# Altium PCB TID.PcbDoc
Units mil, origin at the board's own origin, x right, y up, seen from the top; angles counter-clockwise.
Board outline 2300 x 2000 mil, 2 copper layers (Top Layer, Bottom Layer), stack 62 mil thick; 70 components, 52 nets, 249 pads, 57 vias.
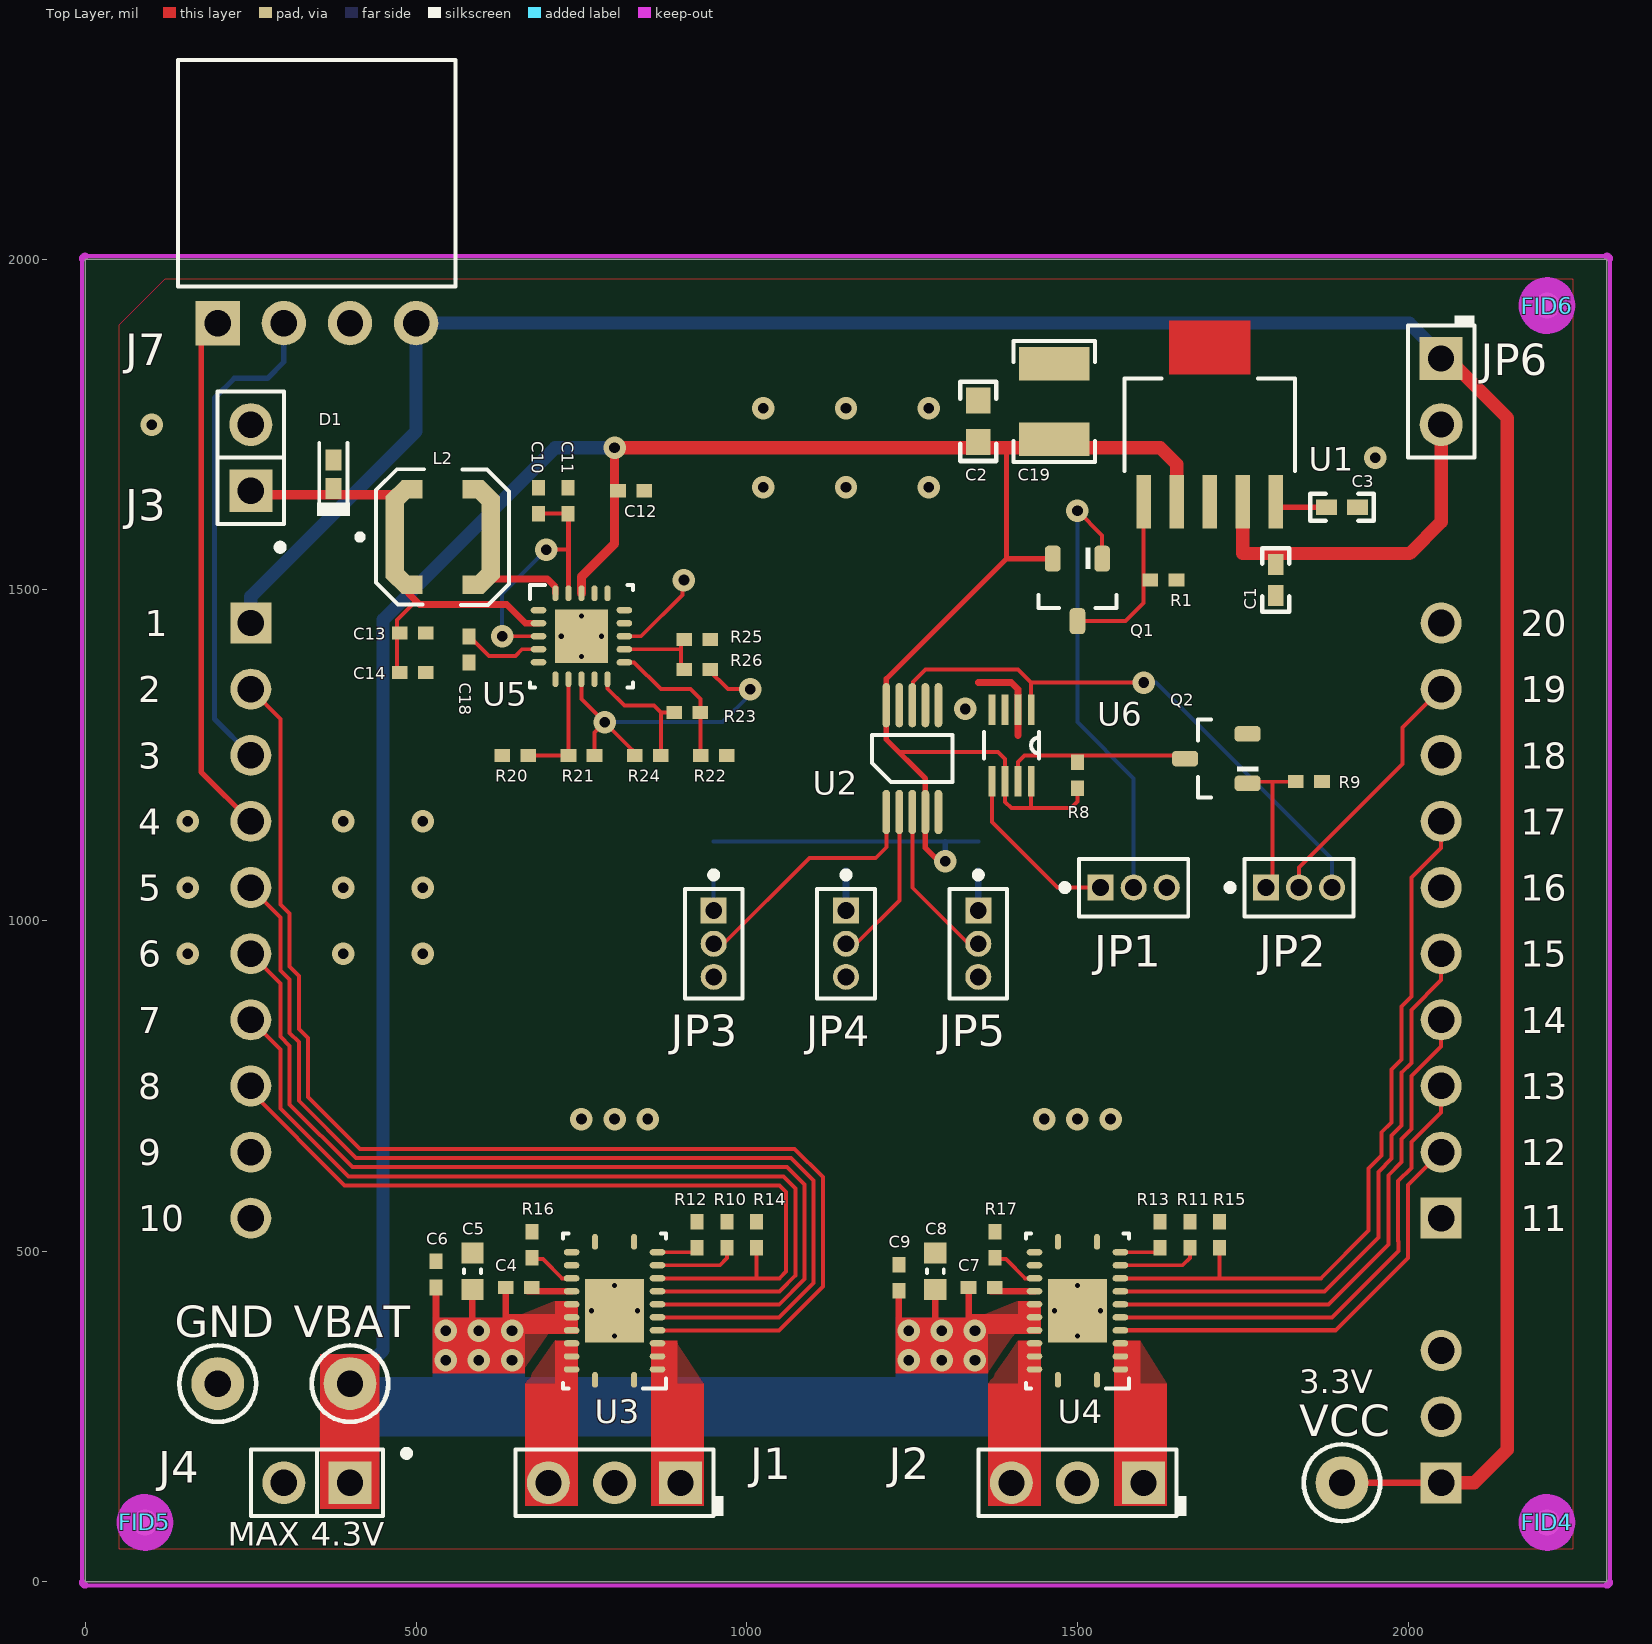
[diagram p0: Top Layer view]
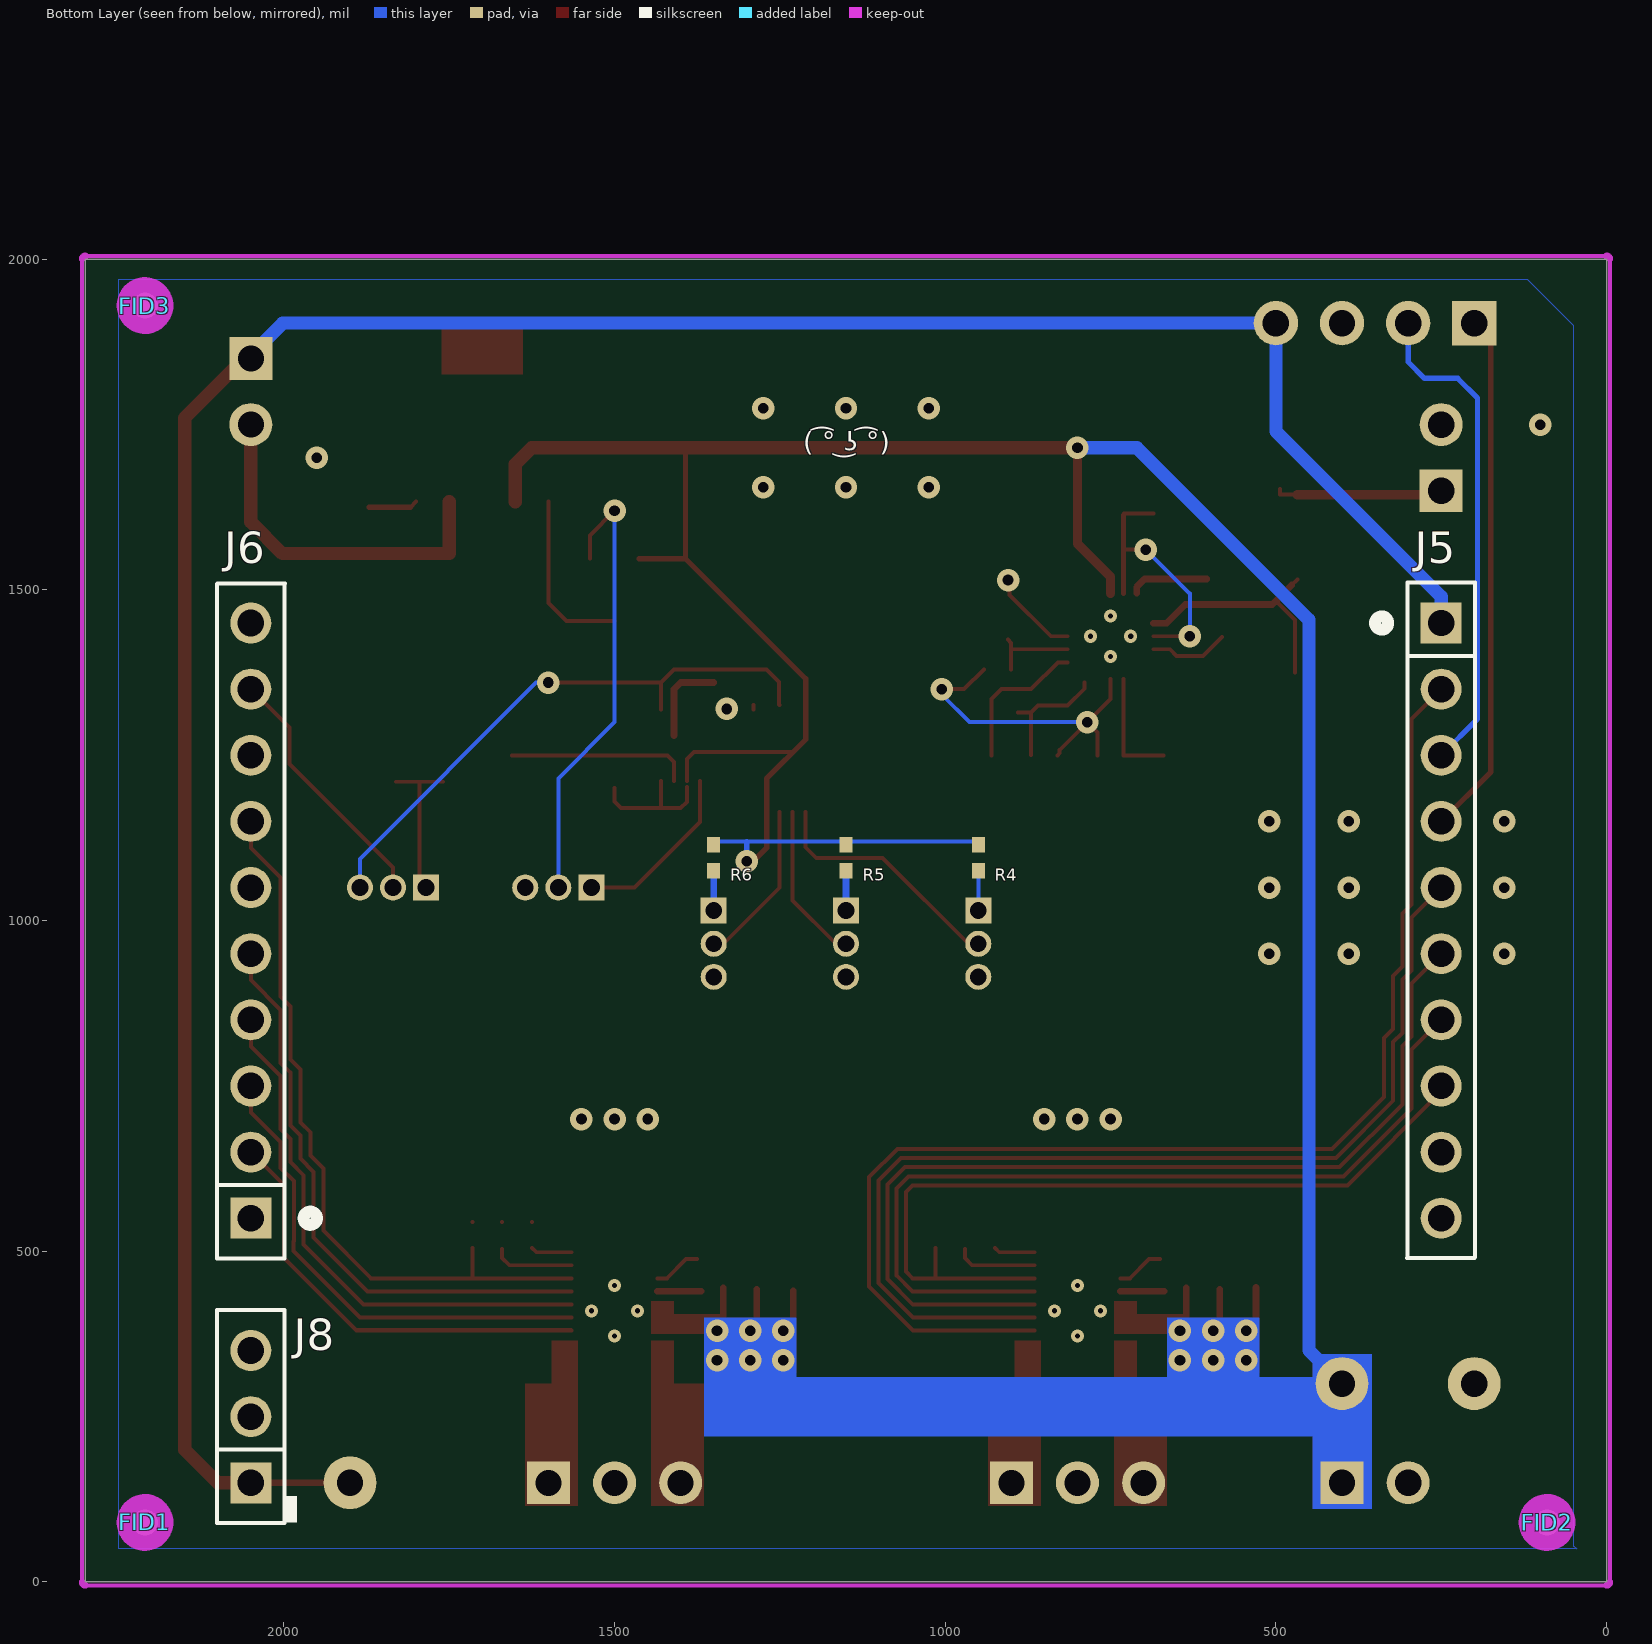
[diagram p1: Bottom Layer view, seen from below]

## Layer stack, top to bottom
Top Solder: solder mask 0.4, Solder Resist, Dk 3.5
Top Layer: signal copper 1.4
Dielectric1: core 59.2, FR-4, Dk 4.8
Bottom Layer: signal copper 1.4
Bottom Solder: solder mask 0.4, Solder Resist, Dk 3.5

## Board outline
0,0 2300,0 2300,2000 0,2000

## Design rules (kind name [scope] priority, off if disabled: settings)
AcuteAngle [All] p1: minimum=4.50000000000000E+0001 checktracksonly=FALSE
AssemblyTestPointUsage [All] p1: valid=2
Clearance Clearance_Keepouts [((IsTrack Or IsArc) And Not InPoly) And IsFree and IsKeepOut vs ((IsTrack Or IsArc) And Not InPoly) And IsFree and IsKeepOut] p1: gap=0
Clearance Clearance_BoardEdge_MountingHoles [OnCopper and InComponentClass('Mounting Holes') vs IsKeepOut] p2: gap=40
Clearance Clearance_BoardEdge_Poly [OnCopper and InPoly vs IsKeepOut] p3: gap=25
Clearance Clearance_BoardEdge [OnCopper and Not InComponentClass('Logo') and not InComponentClass('FiducialMark') and not InRegion(1000,500,4000,800) and Not IsKeepout vs IsKeepOut] p4: gap=30
Clearance Clearance_Poly [InPolygon] p5: gap=10
Clearance [All] p6: gap=7.87
ComponentClearance ComponentClearance_MountingHoles_FiducialMarks [InComponentClass('Mounting Holes') vs InComponentClass('FiducialMark')] p1: gap=50 collisioncheckmode=3 verticalgap=10 showdistances=FALSE
ComponentClearance ComponentClearance_Shunt [InComponentClass('Header') vs InComponentClass('Shunt')] p2: gap=0 collisioncheckmode=3 verticalgap=0 showdistances=FALSE
ComponentClearance ComponentClearance_Logo [InComponentClass('Logo')] p3: gap=50 collisioncheckmode=3 verticalgap=10 showdistances=FALSE
ComponentClearance ComponentClearance_ScrewToNut [(HasFootprint('NY PMS 440 0025 PH')) vs (HasFootprint('Keystone_1902C'))] p4: gap=5 collisioncheckmode=3 verticalgap=10 showdistances=FALSE
ComponentClearance ComponentClearance_MountingHoles [InComponentClass('Mounting Holes')] p5: gap=250 collisioncheckmode=3 verticalgap=100000 showdistances=FALSE
ComponentClearance ComponentClearance_SmallPassives [HasFootprint('0201*') or HasFootprint('0402*') or HasFootprint('0508') or HasFootprint('0603*') or HasFootprint('0612') or HasFootprint('0805*') or HasFootprint('0815*') or HasFootprint('0830*') or HasFootprint('1206*') or HasFootprint('1210*') or HasFootprint('1808*') or HasFootprint('1812*') or HasFootprint('1825*') or HasFootprint('2010*') or HasFootprint('2220*') or HasFootprint('2225*') or HasFootprint('2512*') or HasFootprint('2728*') or HasFootprint('3518*') vs HasFootprint('0201*') or HasFootprint('0402*') or HasFootprint('0508') or HasFootprint('0603*') or HasFootprint('0612') or HasFootprint('0805*') or HasFootprint('0815*') or HasFootprint('0830*') or HasFootprint('1206*') or HasFootprint('1210*') or HasFootprint('1808*') or HasFootprint('1812*') or HasFootprint('1825*') or HasFootprint('2010*') or HasFootprint('2220*') or HasFootprint('2225*') or HasFootprint('2512*') or HasFootprint('2728*') or HasFootprint('3518*')] p6: gap=20 collisioncheckmode=3 verticalgap=10 showdistances=FALSE
ComponentClearance ComponentClearance_THtoSMT [IsThruComponent vs IsSMTComponent] p7: gap=50 collisioncheckmode=3 verticalgap=30 showdistances=FALSE
ComponentClearance ComponentClearance_THtoTH [IsThruComponent vs IsThruComponent] p8: gap=50 collisioncheckmode=3 verticalgap=30 showdistances=FALSE
ComponentClearance [All] p9: gap=40 collisioncheckmode=3 verticalgap=10 showdistances=FALSE
DiffPairsRouting [All] p1: maxlimit=100 minlimit=10 mostfreqgap=10 toplayer_minwidth=15 toplayer_maxwidth=15 toplayer_prefwidth=15 bottomlayer_minwidth=15 bottomlayer_maxwidth=15 bottomlayer_prefwidth=15 maxuncoupledlength=1000
FabricationTestPointUsage TestPointUsage [All] p1: valid=2 allowmultiple=FALSE
FabricationTestpoint Testpoint [All] p1: side=3 testpointundercomponent=TRUE minsize=40 maxsize=100 preferedsize=60 minholesize=0 maxholesize=40 preferedholesize=32 testpointgrid=1 allowsidetop=TRUE allowsidebottom=TRUE usegrid=TRUE gridtolerance=0.01
FanoutControl Fanout_LCC [IsLCC] p1: bgadir=Out bgaviamode=Centered fanoutstyle=Auto fanoutdirection=Alternating viagrid=1 // Fanout_LCC (Default Rule)
FanoutControl Fanout_BGA [IsBGA] p2: bgadir=Out bgaviamode=Centered fanoutstyle=Auto fanoutdirection=Alternating viagrid=1 // Fanout_BGA (Default Rule)
FanoutControl Fanout_Default [All] p4: bgadir=Out bgaviamode=Centered fanoutstyle=Auto fanoutdirection=Alternating viagrid=1 // Fanout_Default (Default Rule)
FanoutControl Fanout_Small [(CompPinCount < 5)] p5: bgadir=Out bgaviamode=Centered fanoutstyle=Auto fanoutdirection=OutThenIn viagrid=1 // Fanout_Small (Default Rule)
HoleSize [All] p1: absolutevalues=TRUE maxlimit=251 minlimit=6 maxpercent=80.000 minpercent=20.000
MinimumAnnularRing MinimumAnnularRing_ThermalPadVias [IsVia and InAnyComponent] p1: minimumring=5.91
MinimumAnnularRing [All] p2: minimumring=6
MinimumSolderMaskSliver MinimumSolderMaskSliver_Logo [InComponentClass('Logo') vs InComponentClass('Logo')] p1: minsoldermaskwidth=0.7
MinimumSolderMaskSliver [All] p2: minsoldermaskwidth=2
PlaneClearance [All] p1: clearance=2
PlaneConnect [All] p1: planeconnectstyle=Direct reliefexpansion=10 reliefentries=4 reliefconductorwidth=10 reliefairgap=10
PolygonConnect [All] p1: connectstyle=Direct reliefconductorwidth=10 reliefentries=4 polygonreliefangle="90 Angle" airgapwidth=10
RoutingVias ThermalPadVias [IsVia and InAnyComponent] p1: holewidth=7.87 width=19.68 viastyle="Through Hole" minholewidth=7.87 minwidth=19.68 maxholewidth=12.99 maxwidth=23.62
RoutingVias [All] p2: holewidth=16 width=34 viastyle="Through Hole" minholewidth=7.87 minwidth=26 maxholewidth=40 maxwidth=65
SilkToBoardRegionClearance [Not ((IsComment or IsDesignator) And (Hide <> 'False')) and not InRegion(1000,500,4000,800)] p1:
SilkToSilkClearance SilkToSilkClearance_Pb-FreeLogo [(HasFootprint('Pb-Free_Overlay_Medium') OR HasFootprint('Pb-Free_Overlay_Small')) vs (HasFootprint('Pb-Free_Overlay_Medium') OR HasFootprint('Pb-Free_Overlay_Small'))] p1: silktosilkclearance=0
SilkToSilkClearance [All] p2: silktosilkclearance=5
SilkToSolderMaskClearance "Silk to Solder Mask Opening" [All] p1: minsilkscreentomaskgap=1 clearancetoexposedcopper=FALSE
SolderMaskExpansion [All] p1: expansion=1.97
UnpouredPolygon [All] p1: allowunpoured=FALSE
Width [All] p1: maxlimit=100 minlimit=6 preferedwidth=10 checkconnectedcopper=TRUE
13 further rules are at their usual default settings.

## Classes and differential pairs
component class FiducialMark: FID1 FID2 FID3 FID4 FID5 FID6
component class "TWO DRV8850 MOTOR DRIVERS": C4 C5 C6 C7 C8 C9 J1 J2 R10 R11 R12 R13 R14 R15 R16 R17 U3 U4
component class "NANO TIMER AND TPS62175": C1 C2 C3 C12 JP1 JP2 JP3 JP4 JP5 JP6 Q1 Q2 R1 R4 R5 R6 R8 R9 U1 U2 U6
component class Header: J1 J2 JP1 JP2 JP3 JP4 JP5 JP6
component class "Energy Harvester": C10 C11 C13 C14 C18 C19 D1 J3 J4 L2 R20 R21 R22 R23 R24 R25 R26 U5 VBAT
component class "Block Diagram": FID1 FID2 FID3 FID4 FID5 FID6 GND J5 J6 J7 J8 VCC

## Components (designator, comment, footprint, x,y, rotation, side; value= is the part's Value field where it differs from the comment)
C1 "C1005X5R0J475M050BC" 0402 1800,1515 r270 top
C2 "GRM188C80J225KE19D" 0603 1350,1755 r90 top
C3 "GRM155R61A103KA01D" 0402 1900,1625 r0 top
C4 "C1005X5R0J104K" 0402L 655,445 r180 top
C5 "C1608X5R1E106M080AC" 0603L 585,470 r90 top
C6 "C1005X5R0J104K" 0402L 530,465 r90 top
C7 "C1005X5R0J104K" 0402L 1355,445 r0 top
C8 "C1608X5R1E106M080AC" 0603L 1285,470 r90 top
C9 "C1005X5R0J104K" 0402L 1230,460 r90 top
C10 "C1005X5R0J475M050BC" 0402L 685,1635 r90 top
C11 "GRM155R71A104KA01D" 0402L 730,1635 r90 top
C12 "GRM155R71A104KA01D" 0402L 825,1650 r0 top
C13 "GRM155R71A104KA01D" 0402L 495,1435 r0 top
C14 "C1005X5R0J475M050BC" 0402L 495,1375 r0 top
C18 "GRM155R61A103KA01D" 0402L 580,1410 r270 top
C19 "C1210C107M9PACTU" 1210 1465,1785 r270 top
D1 "BZT52C4V7T-7" SOD-523 375,1675 r90 top
FID1 "Fiducial" Fiducial10-20 2210,90 r180 bottom
FID2 "Fiducial" Fiducial10-20 90,90 r180 bottom
FID3 "Fiducial" Fiducial10-20 2210,1930 r180 bottom
FID4 "Fiducial" Fiducial10-20 2210,90 r0 top
FID5 "Fiducial" Fiducial10-20 90,90 r0 top
FID6 "Fiducial" Fiducial10-20 2210,1930 r0 top
GND "5001" Keystone5001 200,300 r0 top
J1 "5-146278-3" TE_5-146278-3 800,150 r180 top
J2 "5-146278-3" TE_5-146278-3 1500,150 r180 top
J3 "90120-0122" CONN_90120-0122 250,1700 r90 top
J4 "90120-0122" CONN_90120-0122 350,150 r180 top
J5 "PPTC101LFBN-RC" CONN_PPTC101LFBN-RC 250,1000 r90 bottom
J6 "PPTC101LFBN-RC" CONN_PPTC101LFBN-RC 2050,1000 r270 bottom
J7 "PPPC041LGBN-RC" SULLINS_PPPC041LGBN-RC 350,2120 r180 top
J8 "PPTC031LFBN-RC" Sullins_PPTC031LFBN-RC 2050,250 r270 bottom
JP1 "850-10-003-10-001000" Mill-Max_850-10-003-10-001000 1585,1050 r0 top
JP2 "850-10-003-10-001000" Mill-Max_850-10-003-10-001000 1835,1050 r0 top
JP3 "850-10-003-10-001000" Mill-Max_850-10-003-10-001000 950,965 r270 top
JP4 "850-10-003-10-001000" Mill-Max_850-10-003-10-001000 1150,965 r270 top
JP5 "850-10-003-10-001000" Mill-Max_850-10-003-10-001000 1350,965 r270 top
JP6 "5-146278-2" TE_5-146278-2 2050,1800 r270 top
L2 "LPS4018-223MLB" LPS4018 540,1580 r0 top
Q1 "BSS84-7-F" SOT-23 1500,1500 r270 top
Q2 "2N7002-7-F" SOT-23 1710,1245 r180 top
R1 "CRCW04021M00FKED" 0402L 1630,1515 r180 top
R4 "CRCW040249K9FKED" 0402L 950,1095 r90 bottom
R5 "CRCW040249K9FKED" 0402L 1150,1095 r90 bottom
R6 "CRCW040249K9FKED" 0402L 1350,1095 r90 bottom
R8 "CRCW040249K9FKED" 0402L 1500,1220 r270 top
R9 "CRCW04021M00FKED" 0402L 1850,1210 r0 top
R10 "CRCW04021M00FKED" 0402L 970,525 r90 top
R11 "CRCW04021M00FKED" 0402L 1670,525 r90 top
R12 "CRCW04022R43FKED" 0402L 925,525 r270 top
R13 "CRCW04022R43FKED" 0402L 1625,525 r270 top
R14 "CRCW04021M00FKED" 0402L 1015,525 r270 top
R15 "CRCW04021M00FKED" 0402L 1715,525 r270 top
R16 "ERJ-2RKF1001X" 0402L 675,510 r270 top
R17 "ERJ-2RKF1001X" 0402L 1375,510 r270 top
R20 "CRCW04024M75FKED" 0402L 650,1250 r0 top
R21 "CRCW04028M45FKED" 0402L 750,1250 r0 top
R22 "CRCW04022M10FKED" 0402L 950,1250 r180 top
R23 "CRCW04024M99FKED" 0402L 910,1315 r180 top
R24 "CRCW04021M27FKED" 0402L 850,1250 r180 top
R25 "CRCW04026M49FKED" 0402L 925,1425 r180 top
R26 "CRCW04026M65FKED" 0402L 925,1380 r0 top
U1 "TPS79633_DCQ_6" DCQ6 1700,1750 r0 top
U2 "TPL5100DGS" DGS0010A_N 1250.32,1245 r90 top
U3 "DRV8850RGY" RGY0024B 800,410 r180 top
U4 "DRV8850RGY" RGY0024B 1500,410 r180 top
U5 "BQ25570RGR" RGR0020A 750,1430 r0 top
U6 "SN74AUP1G74_DCU_8" DCU8 1400.32,1265 r270 top
VBAT "5000" Keystone5000 400,300 r0 top
VCC "5000" Keystone5000 1900,150 r0 top

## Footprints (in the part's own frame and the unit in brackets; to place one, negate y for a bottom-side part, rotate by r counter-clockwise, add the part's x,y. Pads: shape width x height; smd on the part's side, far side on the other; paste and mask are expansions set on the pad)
0402 [mm] "0402 from SM-752 data"
  rect 0.8x0.6 smd: 1(-0.6,0) 2(0.6,0)
  silkscreen extent -1.22,-0.52 1.22,0.52, body extent -0.55,-0.3 0.55,0.3, height 0.6
0402L [mm] "0402 from SM-752 data"
  rect 0.6x0.5 smd: 1(-0.5,0) 2(0.5,0)
  body extent -0.55,-0.3 0.55,0.3, height 0.6
0603 [mm] "0603 from SM-752 data"
  rect 1x0.95 smd: 1(-0.8,0) 2(0.8,0)
  silkscreen extent -1.52,-0.69 1.52,0.69, body extent -0.87,-0.47 0.87,0.47, height 0.85
0603L [mm] "0603 from SM-752 data"
  rect 0.8x0.85 smd: 1(-0.7,0) 2(0.7,0)
  silkscreen extent -0.07,-0.33 0.07,0.33, body extent -0.87,-0.47 0.87,0.47, height 0.85
1210 [mm] "1210 from SM-752 data"
  rect 1.3x2.7 smd: 1(-1.45,0) 2(1.45,0)
  silkscreen extent -2.32,-1.57 2.32,1.57, body extent -1.7,-1.35 1.7,1.35, height 1.35
CONN_90120-0122 [mm] "Molex"
  rect 1.65x1.65 hole 1.016 mask+0: 1(-1.27,0)
  round 1.65 hole 1.016 mask+0: 2(1.27,0)
  silkscreen extent -3.56,-1.27 2.54,1.27, body extent -2.54,-1.27 2.54,1.27, height 9.29
CONN_PPTC101LFBN-RC [mil] "SULLINS"
  rect 62x62 hole 40: 1(450,0)
  round 62 hole 40.16: 2(350,0) 3(250,0) 4(150,0) 5(50,0) 6(-50,0) 7(-150,0) 8(-250,0) 9(-350,0) 10(-450,0)
  silkscreen extent -510,-51 511,100, body extent -510,-50 510,50, height 336
DCQ6 [mil]
  rect 22x81 smd: 1(-100,-116.5) 2(-50,-116.5) 3(0,-116.5) 4(50,-116.5) 5(100,-116.5)
  Top Layer region: 61,76 61,157 -61,157 -61,76
  silkscreen extent -129,-70 129,70
DCU8 [mil]
  rect 46x10 smd: 1(-54,29.53) 2(-54,9.84) 3(-54,-9.84) 4(-54,-29.53) 5(54,-29.53) 6(54,-9.84) 7(54,9.84) 8(54,29.53)
  silkscreen extent -20,-41 20,42
DGS0010A_N [mm] "TSSOP, 10-Leads, Body 3x3mm, Pitch 0.5mm, IPC Medium Density"
  oval 1.7x0.3 smd: 1(-2.05,1) 2(-2.05,0.5) 3(-2.05,0) 4(-2.05,-0.5) 5(-2.05,-1) 6(2.05,-1) 7(2.05,-0.5) 8(2.05,0) 9(2.05,0.5) 10(2.05,1)
  silkscreen extent -0.9,-1.55 0.9,1.55, body extent -2.45,-1.5 2.45,1.5, height 0.94
Fiducial10-20 [mm]
  round 1 smd mask+0.5: 1(0,0)
  Top Layer keep-out circle w1.178: c0,0 r0.5
Keystone5000 [mil] "For Keystone 500x miniature loop terminals"
  round 80 hole 40: 1(0,0)
  silkscreen extent -58,-58 58,58, body extent -49,-49 49,49, height 182
Keystone5001 [mil] "For Keystone 500x miniature loop terminals"
  round 80 hole 40: 1(0,0)
  silkscreen extent -58,-58 58,58, body extent -49,-49 49,49, height 182
LPS4018 [mil]
  rect 28x123 smd: 1(-72.5,0) 2(72.5,0)
  rect 35.5x28 smd rot 135: 1(-64,-64) 2(64,64)
  rect 35.5x28 smd rot 45: 1(-64,64) 2(64.5,-63.5)
  rect 31.5x28 smd: 1(-46,-72.5) 1(-46,72.5) 2(46,-72.5) 2(46,72.5)
  silkscreen extent -129,-102 100,102, body extent -81,-81 81,81, height 71
Mill-Max_850-10-003-10-001000 [mm] "Header, 1.27 mm, 3x1, Gold, Straight, TH"
  rect 1x1 hole 0.65: 1(-1.27,0)
  round 1 hole 0.65: 2(0,0) 3(1.27,0)
  silkscreen extent -2.77,-1.1 2.1,1.11, body extent -2.1,-1.1 2.1,1.1, height 5.21
RGR0020A [mm] "QFN, 20-Leads, Body 3.5x3.5mm, Pitch 0.5mm, Thermal Pad 2.05x2.05mm, TI Recommended"
  oval 0.6x0.24 smd: 1(-1.65,1) 2(-1.65,0.5) 3(-1.65,0) 4(-1.65,-0.5) 5(-1.65,-1) 11(1.65,-1) 12(1.65,-0.5) 13(1.65,0) 14(1.65,0.5) 15(1.65,1)
  oval 0.24x0.6 smd: 6(-1,-1.65) 7(-0.5,-1.65) 8(0,-1.65) 9(0.5,-1.65) 10(1,-1.65) 16(1,1.65) 17(0.5,1.65) 18(0,1.65) 19(-0.5,1.65) 20(-1,1.65)
  rect 2.05x2.05 smd paste-1.025: 21(0,0)
  silkscreen extent -1.98,-1.98 1.98,1.98, body extent -1.83,-1.83 1.83,1.83, height 1.01
RGY0024B [mm] "QFN, 24-Leads, Body 5.5x3.5mm, Pitch 0.5mm, Thermal Pad 4.05x2.05mm, TI Recommended"
  oval 0.24x0.6 smd: 1(-0.75,2.65) 12(-0.75,-2.65) 13(0.75,-2.65) 24(0.75,2.65)
  oval 0.6x0.24 smd: 2(-1.65,2.25) 3(-1.65,1.75) 4(-1.65,1.25) 5(-1.65,0.75) 6(-1.65,0.25) 7(-1.65,-0.25) 8(-1.65,-0.75) 9(-1.65,-1.25) 10(-1.65,-1.75) 11(-1.65,-2.25) 14(1.65,-2.25) 15(1.65,-1.75) 16(1.65,-1.25) 17(1.65,-0.75) 18(1.65,-0.25) 19(1.65,0.25) 20(1.65,0.75) 21(1.65,1.25) 22(1.65,1.75) 23(1.65,2.25)
  rect 2.26x2.44 smd paste-1.2: 25(0,0)
  silkscreen extent -1.98,-2.98 1.98,2.98, body extent -1.83,-2.83 1.83,2.82, height 1.01
SOD-523 [mm] "NXP Semiconductor recommended land pattern, nominal STEP model"
  rect 0.8x0.6 smd paste-0.05: 1(-0.55,0) 2(0.55,0)
  silkscreen extent -1.6,-0.64 1.2,0.63, body extent -0.8,-0.4 0.8,0.4, height 0.72
SOT-23 [mm] "SOT23, 3-Leads, Body 2.9x1.3mm, Pitch 0.95mm, Lead Span 2.5mm, IPC Medium Density"
  rrect50% 1x0.6 smd: 1(-1.2,0.95) 2(-1.2,-0.95) 3(1.2,0)
  silkscreen extent -1.63,-1.5 0.7,1.5, body extent -1.16,-1.45 1.21,1.45, height 1
SULLINS_PPPC041LGBN-RC [mm] "Sullins"
  rect 1.7x1.7 hole 1.016: 1(3.81,5.5)
  round 1.7 hole 1.016: 2(1.27,5.5) 3(-1.27,5.5) 4(-3.81,5.5)
  silkscreen extent -5.33,-4.6 5.33,4.1, body extent -5.33,-4.6 5.33,5.7, height 2.56
Sullins_PPTC031LFBN-RC [mil] "SULLINS"
  rect 62x62 hole 40: 1(100,0)
  round 62 hole 40.16: 2(0,0) 3(-100,0)
  silkscreen extent -161,-51 161,70, body extent -160,-50 160,50, height 336
TE_5-146278-2 [mm] "TE CONNECTIVITY"
  rect 1.65x1.65 hole 1: 1(-1.27,0)
  round 1.65 hole 1: 2(1.27,0)
  silkscreen extent -2.92,-1.27 2.54,1.27, body extent -2.41,-1.17 2.41,1.17, height 8.13
TE_5-146278-3 [mm] "TE CONNECTIVITY"
  rect 1.65x1.65 hole 1: 1(-2.54,0)
  round 1.65 hole 1: 2(0,0) 3(2.54,0)
  silkscreen extent -4.19,-1.27 3.81,1.27, body extent -3.68,-1.17 3.68,1.17, height 8.13

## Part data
C1 C10 C14: "CAP, CERM, 4.7uF, 6.3V, +/-20%, X5R, 0402"
C2: "CAP, CERM, 2.2 µF, 6.3 V, +/- 10%, X6S, 0603"
C3 C18: "CAP, CERM, 0.01uF, 10V, +/-10%, X5R, 0402"
C4 C6 C7 C9: "CAP, CERM, 0.1 µF, 6.3 V, +/- 10%, X5R, 0402"
C5 C8: "CAP, CERM, 10 µF, 25 V, +/- 20%, X5R, 0603"
C11 C12 C13: "CAP, CERM, 0.1uF, 10V, +/-10%, X7R, 0402"
C19: "CAP, CERM, 100uF, 6.3V, +/-20%, X5R, 1210"
D1: "Diode, Zener, 4.7V, 300mW, SOD-523"
FID1 FID2 FID3 FID4 FID5 FID6: "Fiducial mark.  There is nothing to buy or mount."
GND: "Test Point, Miniature, Black, TH"
J1 J2: "Header, 100mil, 3x1, Tin, TH"
J3 J4: "Header, 100mil, 2x1, Tin plated, TH"
J5 J6: "Receptacle 100mil 10x1, Tin, TH"
J7: "Receptacle, 100mil, 4x1, Gold, R/A, TH"
J8: "Receptacle, 100mil, 3X1, TH"
JP1 JP2 JP3 JP4 JP5: "Header, 50mil, 3x1, Gold, TH"
JP6: "Header, 100mil, 2x1, Tin, TH"
L2: "Inductor, Shielded Drum Core, Ferrite, 22uH, 0.83A, 0.36 ohm, SMD"
Q1: "MOSFET, P-CH, -50V, -0.13A, SOT-23"
Q2: "MOSFET, N-CH, 60 V, 0.17 A, SOT-23"
R1 R9 R10 R11 R14 R15: "RES, 1.00 M, 1%, 0.063 W, 0402"
R4 R5 R6 R8: "RES, 49.9k ohm, 1%, 0.063W, 0402"
R12 R13: "RES, 2.43, 1%, 0.063 W, 0402"
R16 R17: "RES, 1.00 k, 1%, 0.1 W, 0402"
R20: "RES, 4.75 M, 1%, 0.063 W, 0402"
R21: "RES, 8.45 M, 1%, 0.063 W, 0402"
R22: "RES, 2.10 M, 1%, 0.063 W, 0402"
R23: "RES, 4.99 M, 1%, 0.063 W, 0402"
R24: "RES, 1.27 M, 1%, 0.063 W, 0402"
R25: "RES, 6.49 M, 1%, 0.063 W, 0402"
R26: "RES, 6.65 M, 1%, 0.063 W, 0402"
U1: "Imported"
U2: "Nano Power Programmable Timer, DGS0010A"
U3 U4: "Low-Voltage H-Bridge IC With LDO Regulator, RGY0024B"
U5: "Ultra Low Power Harvester Power Management IC with Boost Charger, and Nano-Powered Buck Converter, RGR0020A"
U6: library part SN74AUP1G74_DCU_, "Imported"
VBAT VCC: "Test Point, Miniature, Red, TH"

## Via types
v1: diameter 34, hole 16, Top Layer to Bottom Layer, 44 vias
v2: diameter 19.68, hole 7.87, Top Layer to Bottom Layer, 12 vias
v3: diameter 34, hole 16, Top Layer to Bottom Layer, tented top, 1 vias

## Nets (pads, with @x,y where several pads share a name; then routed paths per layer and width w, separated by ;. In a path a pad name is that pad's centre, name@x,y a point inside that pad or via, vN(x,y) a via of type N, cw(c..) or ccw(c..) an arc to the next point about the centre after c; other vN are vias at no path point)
A_OUT1: J1.1 U3.2 U3.3 U3.4
A_OUT2: J1.3 U3.21 U3.22 U3.23
B_OUT1: J2.1 U4.2 U4.3 U4.4
B_OUT2: J2.3 U4.21 U4.22 U4.23
GND: C1.2 C2.2 C3.2 C5.2 C6.2 C8.2 C9.2 C10.2 C11.2 C12.2 C13.2 C14.2 C18.2 C19.1 D1.2 GND.1 J1.2 J2.2 J3.2 J4.2 J6.10 J7.3 J8.2 J8.3 JP1.3 JP3.3 JP4.3 JP5.3 Q2.2 R1.1 R9.2 R10.2 R11.2 R12.1 R13.1 R14.1 R15.1 R16.1 R17.1 R20.1 R22.1 R25.1 U1.3 U2.5 U2.6 U3.1 U3.12 U3.13 U3.24 U3.25 U4.1 U4.12 U4.13 U4.24 U4.25 U5.1 U5.5 U5.6 U5.15 U5.21 U6.2 U6.4 | length 176.7
  Top Layer w6: J3.2 277.48,1750 J3.2@277.48,1743.78 ; U2.6@1289.69,1319 U2.6 ; R13.1@1625,544 R13.1 ; R11.2@1670,544 R11.2 ; R15.1@1715,544 R15.1
  Top Layer w10: 1350,1360 1400,1360 1410.16,1349.84 U6.2 1410.16,1280
  other v1: 750,700 800,700 850,700 1450,700 1500,700 1550,700 155,950 390,950 510,950 155,1050 390,1050 510,1050 155,1150 390,1150 510,1150 1330,1320 1025,1655 1275,1655 1950,1700 100,1750 1025,1775 1150,1775 1275,1775
  other v2: 800,371.81 1500,371.81 765.35,410 834.65,410 1465.35,410 1534.65,410 800,448.19 1500,448.19 750,1399.49 719.49,1430 780.51,1430 750,1460.51
  other v3: 1150,1655
M_A_IN1H: J5.2 U3.5 | length 1944.3
  Top Layer w6: J5.2@270,1350 J5.2 295,1305 295,1024.62 308.87,1010.75 308.87,930.37 322.75,916.49 322.75,836.11 336.62,822.24 336.62,733.38 415,655 1072.46,655 1115,612.46 1115,446.52 1048.95,380.47 U3.5
M_A_IN1L: J5.5 U3.6 | length 1593.2
  Top Layer w6: J5.5 295,1005 295,924.62 308.87,910.75 308.87,830.37 322.75,816.49 322.75,727.63 409.25,641.13 1066.72,641.13 1101.13,606.72 1101.13,452.26 1049.02,400.16 U3.6
M_A_IN2H: J5.6 U3.7 | length 1462
  Top Layer w6: J5.6 295,905 295,824.62 308.87,810.75 308.87,721.88 403.51,627.25 1060.97,627.25 1087.25,600.97 1087.25,458.01 1049.08,419.84 U3.7
M_A_IN2L: J5.7 U3.8 | length 1330.9
  Top Layer w6: J5.7 295,805 295,716.14 397.76,613.38 1055.22,613.38 1073.38,595.22 1073.38,463.76 1049.15,439.53 U3.8
M_A_SLEEP: J5.8 R14.2 U3.9 | length 1245.8
  Top Layer w6: J5.8 250,741.52 392.01,599.5 1049.48,599.5 1059.5,589.48 1059.5,469.5 1049.21,459.21 1015,459.21 ; U3.9 1015,459.21 ; R14.2 1015,459.21
M_B_IN1H: J6.2 U4.5 | length 986.6
  Top Layer w6: U4.5 1890.47,380.47 1891,381 ; U4.5@1565.49,381 1891,381 ; J6.2 2000,600 2000,490 1891,381
M_B_IN1L: J6.3 U4.6 | length 738.3
  Top Layer w6: U4.6 1884.88,400.16 1985.12,500.4 1985.12,515.06 1985,515.18 1985,606 2005,626 2005,665 2050,710 J6.3
M_B_IN2H: J6.4 U4.7 | length 815.2
  Top Layer w6: U4.7 1879.29,419.84 1970,510.56 1970,615 1990,635 1990,670 2005,685 2005,765 2050,810 J6.4
M_B_IN2L: J6.5 U4.8 | length 892.2
  Top Layer w6: U4.8 1873.69,439.53 1955,520.83 1955,620 1975,640 1975,675 1990,690 1990,770 2005,785 2005,865 2050,910 J6.5
M_B_SLEEP: J6.7 R15.2 U4.9 | length 1115.4
  Top Layer w6: U4.9 1715,459.21 ; R15.2 1715,459.21 ; J6.7 2050,1110 2005,1065 2005,885 1990,870 1990,790 1975,775 1975,695 1960,680 1960,645 1940,625 1940,531.11 1868.1,459.21 1715,459.21
NetC3_1: C3.1 U1.5 | length 74.9
  Top Layer w6: U1.5 U1.5@1808.5,1625
  Top Layer w8: U1.5@1808.5,1625 C3.1@1871.38,1625
NetC4_1: C4.1 U3.17 | length 66.3
  Top Layer w10: C4.1@668.78,439.53 U3.17
NetC7_2: C7.2 U4.17 | length 66.3
  Top Layer w10: C7.2@1368.78,439.53 U4.17
NetJP1_1: JP1.1 U6.5 | length 267.1
  Top Layer w6: U6.5 1370.79,1149.21 1470,1050 JP1.1
NetJP1_2: JP1.2 Q1.1 | length 693.5
  Top Layer w6: v1(1500,1620) 1537.4,1582.6 Q1.1
  Bottom Layer w6: v1(1500,1620) 1500,1300 1585,1215 JP1.2
NetJP2_1: JP2.1 Q2.1 R9.1 | length 230.7
  Top Layer w6: Q2.1@1759.65,1210 R9.1 ; JP2.1@1795,1050 1795,1210
NetJP2_3: JP2.3 U2.8 U6.1 | length 921.2
  Top Layer w6: U2.8 1251.22,1326.61 1251.22,1361.05 1270.17,1380 1410,1380 1430,1360 U6.1@1430,1319.16 ; U6.1 1429.84,1359.42 1430.42,1360 v1(1600,1360)
  Bottom Layer w6: v1(1600,1360) 1618.5,1360 1885,1093.5 JP2.3
NetJP3_1: JP3.1 R4.1 | length 60.3
  Bottom Layer w6: JP3.1 R4.1
NetJP3_2: JP3.2 U2.1 | length 359.7
  Top Layer w6: JP3.2@965,965 1095,1095 1195,1095 1210.94,1110.94 U2.1
NetJP4_1: JP4.1 R5.1 | length 60.3
  Bottom Layer w10: JP4.1 R5.1
NetJP4_2: JP4.2 U2.2 | length 226.5
  Top Layer w6: JP4.2@1165,965 1230.63,1030.63 U2.2
NetJP5_1: JP5.1 R6.1 | length 60.3
  Bottom Layer w10: JP5.1 R6.1
NetJP5_2: JP5.2 U2.3 | length 249.4
  Top Layer w6: U2.3 1250.32,1049.68 1335,965 JP5.2
NetL2_2: L2.2 U5.20 | length 128.6
  Top Layer w6: L2.2@604.5,1516.5 L2.2@612.5,1516.5
  Top Layer w10: L2.2@604.5,1516.5 698.5,1516.5 710.63,1504.37 U5.20
NetQ1_3: Q1.3 R1.2 U1.1 | length 264.8
  Top Layer w6: Q1.3 1572.76,1452.76 1600,1480 U1.1
NetQ2_3: Q2.3 R8.1 U6.7 | length 278.1
  Top Layer w6: U6.7 1410.16,1240.16 1420,1250 Q2.3@1655,1250
NetR10_1: R10.1 U3.10 | length 123.2
  Top Layer w6: U3.10 959.33,478.9 970,489.57 R10.1@970,503.35
NetR11_1: R11.1 U4.10 | length 123
  Top Layer w6: U4.10 1658.9,478.9 1670,490 R11.1@1670,503.35
NetR12_2: R12.2 U3.11 | length 62.8
  Top Layer w6: U3.11 918.27,498.58 R12.2
NetR13_2: R13.2 U4.11 | length 62.8
  Top Layer w6: U4.11 1618.27,498.58 R13.2
NetR16_2: R16.2 U3.16 | length 72.1
  Top Layer w6: R16.2@675,488.37 691.63,488.37 720.79,459.21 U3.16
NetR17_2: R17.2 U4.16 | length 72.1
  Top Layer w6: R17.2@1375,488.37 1391.63,488.37 1420.79,459.21 U4.16
OK_HYST: R23.2 R24.1 U5.10 | length 189.8
  Top Layer w6: U5.10@789.37,1360.04 789.37,1350.63 815,1325 860,1325 870,1315 ; R24.1@870,1250.32 870,1315 ; R23.2 870,1315
OK_PROG: R22.2 R23.1 U5.11 | length 223
  Top Layer w6: U5.11 829.37,1390.63 870,1350 915,1350 929.68,1335.32 R22.2@929.68,1250
RX: J5.3 J7.2 | length 772.5
  Bottom Layer w8: J5.3 195,1305 195,1790 225,1820 275,1820 300,1845 J7.2 J7.2@300,1880
TX: J5.4 J7.1 | length 795.4
  Top Layer w8: J7.1 200,1903.11 175,1878.11 175,1225 J5.4
  Bottom Layer w8: J7.1@199.65,1903.11 J7.1
UCONTROLLER: J6.9 JP2.2 | length 389.1
  Top Layer w6: JP2.2 1835,1080 1991.75,1236.74 1991.75,1291.75 J6.9
VBAT: C2.1 C4.2 C5.1 C6.1 C7.1 C8.1 C9.1 C12.1 C19.2 J4.1 Q1.2 R4.2 R5.2 R6.2 R8.2 U1.2 U2.4 U2.10 U3.18 U3.19 U3.20 U4.18 U4.19 U4.20 U5.18 U6.6 U6.8 VBAT.1 | length 4791.3
  Top Layer w6: J4.1@373,177 J4.1 ; 1230,1255 1380,1255 1390.47,1244.53 U6.6 ; U6.6@1390.47,1202 1390.47,1179.53 1400,1170 1430,1170 ; U6.8@1430,1210.84 1430,1170 ; R8.2 1500,1180 1490,1170 1430,1170
  Top Layer w8: v1@1290,1090 1270,1110 1270,1215 1210.94,1274.06 1210.94,1365.59 1392.6,1547.24 ; 1392.6,1715 1392.6,1547.24 ; Q1.2 1392.6,1547.24
  Top Layer w10: 530,390 C6.1 ; v1@585,390 C5.1 ; v1@635.31,385.31 C4.2 ; 1230,395 C9.1 ; v1@1285,390 C8.1 ; v1@1290,1090 v1(1300,1090) ; v1@1335.32,390.32 C7.1
  Top Layer w14: U5.18 750,1520 800,1570 v1(800,1715)
  Top Layer w20: v1@795,1715 1625,1715 1650,1690 U1.2
  Bottom Layer w6: R4.2@950,1119.69 1300,1119.69 R6.2@1350,1119.69
  Bottom Layer w8: v1(1300,1090) 1300,1119.69
  Bottom Layer w20: VBAT.1 450,350 450,1455 710,1715 v1@795,1715
  other v1: 545,335 595,335 645,335 1245,335 1295,335 1345,335 545,380 595,380 645,380 1245,380 1295,380 1345,380
VBAT_OK: U5.13 | length 123.4
  Top Layer w6: U5.13 840,1430 902.48,1492.48 v1@902.48,1502.52
  other v1: 905,1515
VBAT_OV: R20.2 R21.1 U5.7 | length 175.7
  Top Layer w6: R20.2 R21.1 U5.7
VCC: J5.1 J7.4 J8.1 JP6.1 VCC.1 | length 4122
  Top Layer w10: VCC.1 J8.1
  Top Layer w20: J7.4 J7.4@516.54,1920 ; J8.1 2100,150 2150,200 2150,1760 2060,1850 JP6.1
  Bottom Layer w20: J5.1 250,1490 500,1740 J7.4 2001.54,1903.46 JP6.1@2052.5,1852.5
VIN: C13.1 C14.1 D1.1 J3.1 L2.1 U5.2 | length 639.3
  Top Layer w6: J3.1 J3.1@256,1644 ; L2.1@467.5,1516 L2.1@476,1507.5 ; L2.1@467.5,1644 476,1644 494,1644 L2.1@494,1652.5 ; C14.1@471.38,1375 471.38,1454.88 500,1483.5
  Top Layer w10: L2.1@476,1507.5 500,1483.5 505.5,1478 637,1478 665.31,1449.69 U5.2
  Top Layer w14: J3.1@256,1644 L2.1@467.5,1644
  Bottom Layer w6: J3.1@231,1650 J3.1
VOS: C1.1 JP6.2 U1.4 | length 550.5
  Top Layer w10: JP6.2 JP6.2@2055,1750
  Top Layer w20: U1.4 1750,1555 2002.24,1555 2050,1602.76 JP6.2
VOUT_SET: R25.2 R26.1 U5.12 | length 132.4
  Top Layer w6: U5.12 900.32,1410.32 ; R26.1@900.32,1380 900.32,1420 R25.2
VR_DIV: R21.2 R24.2 R26.2 U5.8 | length 526.1
  Top Layer w6: U5.8 750,1335 826.83,1258.17 826.83,1253.48 R24.2 ; R21.2 769.69,1284.69 v1(785,1300) ; R26.2@941.64,1380.01 971.65,1350 v1(1005,1350)
  Bottom Layer w6: v1(785,1300) 963.5,1300 1005,1341.5 v1(1005,1350)
VREF_SAMP: C18.1 U5.4 | length 120.1
  Top Layer w6: C18.1@581.14,1428.86 610,1400 650,1400 660.32,1410.32 U5.4
VSTOR: C10.1 C11.1 U5.3 U5.19 | length 410.3
  Top Layer w6: v1(630,1430) U5.3 ; C10.1 C11.1 ; v1(697,1561) 730.31,1561
  Top Layer w8: U5.19 730.31,1561 C11.1@730.31,1613.35
  Bottom Layer w6: v1(630,1430) 630,1494.5 ; 630.5,1494.5 v1(697,1561)
pads on no net: FID1.1 FID2.1 FID3.1 FID4.1 FID5.1 FID6.1 J5.9 J5.10 J6.1 J6.6 J6.8 U2.7 U2.9 U3.14 U3.15 U4.14 U4.15 U5.9 U5.14 U5.16 U5.17 U6.3

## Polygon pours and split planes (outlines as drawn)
GND on Top Layer "Top Layer-GND" (solid, shelved, pour order 15): 2250,1970 120,1970 50,1900 50,50 2250,50
A_OUT2 on Top Layer "A_OUT2" (solid, pour order 18): 665,300 710,365 710,300
B_OUT2 on Top Layer "B_OUT2" (solid, pour order 17): 1365,300 1410,365 1410,300
VBAT on Top Layer "B_VBAT1" (solid, pour order 22): 1410,425 1360,405 1410,405
B_OUT1 on Top Layer "B_OUT1" (solid, pour order 16): 1635,300 1595,365 1595,300
A_OUT1 on Top Layer "A_OUT1" (solid, pour order 13): 935,300 895,360 895,300
VBAT on Top Layer "A_VBAT2" (solid, pour order 21): 665,325 700,375 665,375
VBAT on Top Layer "B_VBAT2" (solid, pour order 20): 1365,315 1405,375 1365,375
VBAT on Top Layer "A_VBAT1" (solid, pour order 19): 710,425 660,405 710,405
GND on Bottom Layer "Btm GND" (solid, shelved, pour order 23): 2250,50 2250,1970 120,1970 50,1900 50,55 45,50

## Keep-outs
Keep-Out Layer:
  lines w6: -5,0 -5,2000 ; 0,-5 2300,-5 ; 0,2005 2300,2005 ; 2305,0 2305,2000
  lines w10: -5,0 ccw(c0,0) 0,-5 cw(c0,0) -5,0 ; -5,2000 cw(c0,2000) 0,2005 ccw(c0,2000) -5,2000 ; 2300,-5 ccw(c2300,0) 2305,0 cw(c2300,0) 2300,-5 ; 2300,2005 cw(c2300,2000) 2305,2000 ccw(c2300,2000) 2300,2005
  text ".Layer_Name" at 577,-858.49 h60

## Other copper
Top Layer:
  rectangle net VBAT: 525,315 665,400
  rectangle net VBAT: 710,375 745,425
  rectangle net A_OUT2: 710,300 745,365
  rectangle net A_OUT2: 665,115 745,300
  rectangle net B_OUT2: 1365,115 1445,300
  rectangle net B_OUT2: 1410,300 1445,365
  rectangle net VBAT: 1225,315 1365,400
  rectangle net VBAT: 1410,375 1445,425
  rectangle net VBAT: 635,375 710,405
  rectangle net VBAT: 1335,375 1410,405
  rectangle net B_OUT1: 1555,115 1635,300
  rectangle net B_OUT1: 1555,300 1595,365
  rectangle net A_OUT1: 855,115 935,300
  rectangle net A_OUT1: 855,300 895,365
  rectangle net VBAT: 355,110 445,345
  text ".Layer_Name" at 577,-858.49 h60
Bottom Layer:
  rectangle net VBAT: 1225,250 1365,400
  rectangle net VBAT: 360,220 1365,310
  rectangle net VBAT: 355,110 445,345
  rectangle net VBAT: 525,250 665,400
  text ".Layer_Name" at 577,-858.49 h60

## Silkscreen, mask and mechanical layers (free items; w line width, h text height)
Top Overlay:
  text "1" at 90,1430 h40
  text "20" at 2170,1430 h40
  text "2" at 80,1330 h40
  text "19" at 2170,1330 h40
  text "3" at 80,1230 h40
  text "18" at 2170,1230 h40
  text "4" at 80,1130 h40
  text "17" at 2170,1130 h40
  text "5" at 80,1030 h40
  text "16" at 2170,1030 h40
  text "6" at 80,930 h40
  text "15" at 2170,930 h40
  text "7" at 80,830 h40
  text "14" at 2170,830 h40
  text "8" at 80,730 h40
  text "13" at 2170,730 h40
  text "9" at 80,630 h40
  text "12" at 2170,630 h40
  text "10" at 80,530 h40
  text "11" at 2170,530 h40
  text "3.3V" at 1835,285 h36
  text "MAX 4.3V" at 215,55 h36
  text ".Layer_Name" at 577,-858.49 h60
Bottom Overlay:
  text "( ͡° ͜ʖ ͡°)" at 1215,1700 h50
  text ".Layer_Name" at 577,-858.49 h60
Top Paste:
  text ".Layer_Name" at 577,-858.49 h60
Bottom Paste:
  text ".Layer_Name" at 577,-858.49 h60
Top Solder:
  text ".Layer_Name" at 577,-858.49 h60
  text ".Layer_Name" at 577,-858.49 h60
Bottom Solder:
  text ".Layer_Name" at 577,-858.49 h60
Drill Guide:
  text ".Layer_Name" at 577,-858.49 h60
M1 Board Outline:
  the board outline again, w6
  text ".Layer_Name" at 577,-858.49 h60
M2 Board Dimensions:
  rectangle: 125,-400 500,-275
  rectangle: 0,-275 125,-150
  lines w6: 0,-275 1000,-275 ; 125,-400 125,-150 ; 250,-400 250,-150 ; 500,-400 500,-150 ; 750,-400 750,-150 ; 0,-400 0,-150 1000,-150 1000,-400 0,-400
  text ".Layer_Name" at 577,-858.49 h60
M3 3D STEP Top:
  text ".Layer_Name" at 577,-858.49 h60
M4 3D STEP Bottom:
  text ".Layer_Name" at 577,-858.49 h60
M5 Assembly Top:
  lines w6: -292,-930.17 6308,-930.17 ; -292,-726.83 6310,-726.83 ; -292,-523.5 -292,-1133.5 3713,-1133.5 6310,-1133.5 6310,-523.5 -291.5,-523.5 -291.5,-1133.5 1284,-1133.5 ; 2173,-1133.5 2173,-523.5 ; 3440,-726.83 3440,-523.5 ; 4280,-726.83 4280,-523.5 ; 4902,-1140 4902,-937.17
  text "COMPONENTS MARKED 'DNP' SHOULD NOT BE POPULATED." at 1153.5,-318.5 h60
  text "ASSEMBLY VARIANT:" at 1153,-434 h60
  text ".VariantName" at 2189,-434 h60
  text "PCB VIEWED FROM TOP SIDE" at -228.5,-655.67 h60
  text "BOARD #:" at 2248,-655.67 h60
  text ".PRJ_Number" at 2793.5,-655.67 h60
  text "REV:" at 3638,-655.67 h60
  text ".PCB_Rev" at 3929.5,-655.67 h60
  text "SVN REV:" at 4476,-655.67 h60
  text ".VersionControl_RevNumber" at 4982,-655.67 h60
  text "PLOT NAME =" at -228.5,-1064.34 h60
  text ".plot_File_Name" at 577,-1064.34 h60
  text "GENERATED    :" at 2250,-1064.34 h60
  text ".Print_Date" at 3119.5,-1064.34 h60
  text ".Print_Time" at 3848.5,-1064.34 h60
  text "TEXAS INSTRUMENTS" at 5113,-1064.34 h60
M6 Assembly Bottom:
  lines w6: -292.5,-727.33 6309.5,-727.33 ; -290.5,-930.67 6309.5,-930.67 ; 1115.5,-1140.5 1115.5,-937.67 ; 1737.5,-727.33 1737.5,-524 ; 2577.5,-727.33 2577.5,-524 ; 3844.5,-1134 3844.5,-524 ; 4733.5,-1134 6309,-1134 6309,-524 -292.5,-524 -292.5,-1134 2304.5,-1134 6309.5,-1134 6309.5,-524
  text "COMPONENTS MARKED 'DNP' SHOULD NOT BE POPULATED." at 6102,-318 h60
  text ".VariantName" at 5058,-434 h60
  text "ASSEMBLY VARIANT:" at 6097,-434 h60
  text ".VersionControl_RevNumber" at 1035.5,-656.17 h60
  text "SVN REV:" at 1541.5,-656.17 h60
  text ".PCB_Rev" at 2088,-656.17 h60
  text "REV:" at 2379.5,-656.17 h60
  text ".PRJ_Number" at 3224,-656.17 h60
  text "BOARD #:" at 3769.5,-656.17 h60
  text "PCB VIEWED FROM BOTTOM SIDE" at 6246,-656.17 h60
  text "TEXAS INSTRUMENTS" at 904.5,-1064.84 h60
  text ".Print_Time" at 2169,-1064.84 h60
  text ".Print_Date" at 2898,-1064.84 h60
  text "GENERATED    :" at 3767.5,-1064.84 h60
  text ".plot_File_Name" at 5440.5,-1064.84 h60
  text "PLOT NAME =" at 6246,-1064.84 h60
M9 Title Sheet:
  drawing of 57 lines, arcs and shapes, not listed
  text "1" at 739.84,8036.5 h70
  text "2" at 3235.5,8036.5 h70
  text "3" at 5724.84,8036.5 h70
  text "4" at 8231.51,8036.5 h70
  text "5" at 10730.5,8036.5 h70
  text "6" at 13235.5,8036.5 h70
  text "A" at -416.5,6893.5 h70
  text "A" at 14383.5,6893.5 h70
  text "B" at -416.5,4513.5 h70
  text "B" at 14383.5,4513.5 h70
  text "C" at -416.5,2138.5 h70
  text "C" at 14383.5,2138.5 h70
  text "PROJECT TITLE:" at 11343.5,277.5 h45
  text ".PRJ_Title" at 11393.5,144.17 h70
  text "DESIGNED FOR:" at 11343.5,-23.5 h45
  text ".PRJ_Customer" at 11393.5,-163.5 h70
  text "D" at -416.5,-231.5 h70
  text "D" at 14383.5,-231.5 h70
  text "FILE NAME:" at 11343.5,-323.5 h45
  text ".PCB_File_Name_No_Path" at 11393.5,-443.5 h70
  text "Texas Instruments (TI) and/or its licensors do not warrant the accuracy or completeness of this specification" at 6374,-605.34 h45
  text "ENGINEER:" at 11343.5,-613.5 h45
  text "LAYOUT BY:" at 12848.5,-613.5 h45
  text "or any information contained therein. TI and/or its licensors do not warrant that this design will meet" at 6329.01,-718 h45
  text ".PRJ_Engineer" at 11393.5,-768.49 h70
  text ".PCB_Layout" at 12899,-768.49 h70
  text "the specifications, will be suitable for your application or fit for any particular purpose, or will operate in" at 6329.01,-830.67 h45
  text ".Layer_Name" at 577,-858.49 h60
  text "ALTIUM DESIGNER VERSION:" at 12848.5,-923.5 h45
  text "an implementation. TI and/or its licensors do not warrant that the design is production worthy. You should" at 6329.01,-943.33 h45
  text "completely validate and test your design implementation to confirm the system functionality for your application." at 6374,-1056 h45
  text ".print_Scale" at 11393.5,-1056.83 h70
  text ".Application_BuildNumber" at 12899,-1056.83 h70
  text "1" at 739.84,-1263.5 h70
  text "2" at 3235.5,-1263.5 h70
  text "3" at 5724.84,-1263.5 h70
  text "4" at 8231.51,-1263.5 h70
  text "5" at 10730.5,-1263.5 h70
  text "6" at 13235.5,-1263.5 h70
M10 Fab Notes:
  drawing of 185 lines, arcs and shapes, not listed
  text "DESIGN INFORMATION" at 12381.02,5910 h60
  text "MIN. TRACK WIDTH:" at 11736.46,5730 h60
  text "8" at 12832.7,5730 h60
  text "MIL" at 12987.46,5730 h60
  text "MIN. CLEARANCE:" at 11736.46,5598 h60
  text "0.2" at 12772.7,5598 h60
  text "mm" at 12987.46,5598 h60
  text "MIN. VIA PAD SIZE:" at 11736.46,5466 h60
  text "24" at 12802.71,5466 h60
  text "MIL" at 12987.46,5466 h60
  text "0.05mm (2MIL)" at 12431.46,5324.29 h60
  text "MINIMUM ANNULAR RING" at 11407.23,5320 h60
  text "EXTERNAL" at 13139.46,5320 h60
  text "PER" at 11607.23,5202 h60
  text "IPC-D-275 CLASS 2 LEVEL C" at 11827.23,5202 h60
  text "MIL, HOLES" at 13315.46,5089.71 h60
  text "+/-" at 12923,5089 h60
  text "+/-" at 13777,5089 h60
  text "REGISTRATION TOLERANCES:" at 11407.23,5084 h60
  text "METAL" at 12607,5084 h60
  text "5" at 13183.2,5084 h60
  text "3" at 14016.2,5084 h60
  text "MIL" at 14132.46,5084 h60
  text "MATERIAL:" at 11332.46,4874.54 h60
  text "FR-4 High Tg" at 12318.9,4734.21 h60
  text "FR-408" at 11753.46,4725.64 h60
  text "X" at 12165.46,4725.64 h60
  text "OTHER" at 13241.46,4725.64 h60
  text "62 MIL (1.6mm) +/-10%" at 12073.56,4562.92 h60
  text "THICKNESS:" at 11407.23,4558.64 h60
  text "X" at 11945.4,4558.64 h60
  text "OTHER" at 13358.46,4558.64 h60
  text "TOLERANCE:" at 11407.23,4400.64 h60
  text "X" at 12246.53,4400.64 h60
  text "ANSI IPC-6012 TYPE 3 CLASS 2" at 12433.48,4400.64 h60
  text "OTHER +/-" at 12433.46,4244.64 h60
  text "BOW & TWIST:" at 11407.23,4087.64 h60
  text "X" at 12246.53,4087.64 h60
  text "ANSI IPC-6012 TYPE 3 CLASS 2" at 12433.48,4087.64 h60
  text "OTHER +/-" at 12433.46,3929.13 h60
  text "DRILLING:" at 11332.46,3790.64 h60
  text "REFERENCE:" at 11407.23,3673.64 h60
  text "X" at 12055.46,3673.64 h60
  text "AS SHOWN" at 12242.46,3673.64 h60
  text "X" at 12956.46,3673.64 h60
  text "NC_DRILL FILES" at 13093.46,3673.64 h60
  text "PTH MIN COPPER THICKNESS:" at 11407.23,3515.64 h60
  text "X" at 12757.46,3515.64 h60
  text "1MIL" at 12894.46,3515.64 h60
  text "OTHER" at 13391.46,3515.64 h60
  text "BOARD FINISH:" at 11332.46,3356.64 h60
  text "SILKSCREEN:" at 11487.68,3238.64 h60
  text "X" at 12436.46,3238.64 h60
  text "TOP" at 12562.46,3238.64 h60
  text "X" at 12946.46,3238.64 h60
  text "BOTTOM" at 13073.46,3238.64 h60
  text "SILKSCREEN COLOR:" at 11487.68,3071.64 h60
  text "X" at 12435.42,3071.64 h60
  text "WHITE" at 12562.46,3071.64 h60
  text "OTHER" at 13073.46,3071.64 h60
  text "SOLDER RESIST COLOR:" at 11487.68,2901.64 h60
  text "X" at 12055.42,2742.44 h60
  text "GREEN" at 12182.46,2742.44 h60
  text "BLUE" at 12773.46,2742.44 h60
  text "OTHER" at 13311.46,2742.44 h60
  text "IMMERSION GOLD (ENIG)" at 12393.46,2553.92 h60
  text "ENEPIG" at 13731,2550.64 h60
  text "SURFACE FINISH:" at 11332.46,2549.64 h60
  text "X" at 12206.51,2549.64 h60
  text "IMM. TIN/SILVER OR EQUIV" at 11662,2392.64 h60
  text "OTHER" at 13093.46,2392.64 h60
  text "ARRAY/PANEL:" at 11332.46,2213.64 h60
  text "CUT AND TRIM PER MECH LAYER 1" at 12393.46,2209.35 h60
  text "N.C. ROUTE" at 12393.46,2057.64 h60
  text "X" at 13072.46,2057.64 h60
  text "V. SCORE" at 13259.46,2057.64 h60
  text "CERTIFICATION:" at 11332.46,1920.64 h60
  text "MATERIALS AND WORKMANSHIP FOR ALL PCBS" at 12057.46,1920.64 h60
  text "TO MEET OR EXCEED THE REQUIREMENTS OF:" at 12057.46,1822.64 h60
  text "X" at 11683.96,1686.13 h60
  text "ANSI IPC-A-600F CLASS ->" at 11822.96,1686.13 h60
  text "X" at 13462.02,1686.13 h60
  text "2" at 13580.96,1686.14 h60
  text "1" at 13265.96,1684.64 h60
  text "3" at 13934.96,1684.64 h60
  text "X" at 11686.02,1526.64 h60
  text "UL 94V-0" at 11822.96,1526.64 h60
  text "X" at 12498.02,1526.64 h60
  text "RoHS" at 12634.96,1526.64 h60
  text "OTHER" at 13279.36,1526.64 h60
  text "PER ORDER" at 13676.42,1526.64 h60
  text "ADDITIONAL REQUIREMENTS:" at 11332.46,1385.64 h60
  text "MICROSECTION:" at 11407.23,1270.64 h60
  text "YES" at 12312.96,1270.64 h60
  text "REQUIRED" at 13174.46,1114.49 h60
  text "BARE BOARD ELEC. TEST:" at 11407.23,1111.64 h60
  text "NONE" at 12712.96,1111.64 h60
  text "X" at 13047.46,1111.64 h60
  text "PER ORDER" at 13766.46,1111.64 h60
  text "MANUFACTURER'S UL:" at 11407.23,954.64 h60
  text "RAIL" at 12572.96,950.35 h60
  text "METAL" at 13064.77,950.35 h60
  text "X" at 13440,950 h60
  text "SILK" at 13576.46,950.35 h60
  text ".Layer_Name" at 577,-858.49 h60
M11 Gerber Information:
  lines w6: -292,-930.17 6308,-930.17 ; -292,-726.83 6310,-726.83 ; -292,-523.5 -292,-1133.5 3713,-1133.5 6310,-1133.5 6310,-523.5 -291.5,-523.5 -291.5,-1133.5 1284,-1133.5 ; 2173,-1133.5 2173,-523.5 ; 3440,-726.83 3440,-523.5 ; 4280,-726.83 4280,-523.5 ; 4902,-1140 4902,-937.17
  text "ALL ARTWORK VIEWED FROM TOP SIDE" at -228.5,-655.67 h60
  text "BOARD #:" at 2248,-655.67 h60
  text ".PRJ_Number" at 2793.5,-655.67 h60
  text "REV:" at 3638,-655.67 h60
  text ".PCB_Rev" at 3929.5,-655.67 h60
  text "SVN REV:" at 4476,-655.67 h60
  text ".VersionControl_RevNumber" at 4982,-655.67 h60
  text "LAYER NAME =" at -228.5,-858.49 h60
  text "PLOT NAME =" at -228.5,-1064.34 h60
  text ".plot_File_Name" at 577,-1064.34 h60
  text "GENERATED    :" at 2250,-1064.34 h60
  text ".Print_Date" at 3119.5,-1064.34 h60
  text ".Print_Time" at 3848.5,-1064.34 h60
  text "TEXAS INSTRUMENTS" at 5113,-1064.34 h60
M12 Stackup:
  drawing of 191 lines, arcs and shapes, not listed
  text "Layer" at 9790.58,7830 h60
  text "Name" at 10200.49,7830 h60
  text "Material" at 11130.23,7830 h60
  text "Thickness" at 11990,7830 h60
  text "Constant" at 12639.84,7830 h60
  text "Board Layer Stack" at 13209.7,7830 h60
  text "1" at 9790.58,7710 h60
  text "Top Overlay" at 10200.49,7710 h60
  text "2" at 9790.58,7590 h60
  text "Top Solder" at 10200.49,7590 h60
  text "Solder Resist" at 11130.23,7590 h60
  text "0.40mil" at 11990,7590 h60
  text "3.5" at 12639.84,7590 h60
  text "3" at 9790.58,7470 h60
  text "Top Layer" at 10200.49,7470 h60
  text "Copper" at 11130.23,7470 h60
  text "1.40mil" at 11990,7470 h60
  text "4" at 9790.58,7350 h60
  text "Dielectric1" at 10200.49,7350 h60
  text "FR-4" at 11130.23,7350 h60
  text "59.20mil" at 11990,7350 h60
  text "4.8" at 12639.84,7350 h60
  text "5" at 9790.58,7230 h60
  text "Bottom Layer" at 10200.49,7230 h60
  text "Copper" at 11130.23,7230 h60
  text "1.40mil" at 11990,7230 h60
  text "6" at 9790.58,7110 h60
  text "Bottom Solder" at 10200.49,7110 h60
  text "Solder Resist" at 11130.23,7110 h60
  text "0.40mil" at 11990,7110 h60
  text "3.5" at 12639.84,7110 h60
  text "7" at 9790.58,6990 h60
  text "Bottom Overlay" at 10200.49,6990 h60
  text ".Layer_Name" at 577,-858.49 h60
M13 Component Bodies Top:
  text ".Layer_Name" at 577,-858.49 h60
M14 Component Bodies Bottom:
  text ".Layer_Name" at 577,-858.49 h60
M15 Courtyards Top:
  text ".Layer_Name" at 577,-858.49 h60
M16 Courtyards Bottom:
  text ".Layer_Name" at 577,-858.49 h60
Drill Drawing:
  circle w1: c5557.72,3259.38 r20.72
  lines w1: 5537,2627.42 5547.36,2627.42 5547.36,2617.06 5568.08,2617.06 5568.08,2627.42 5578.44,2627.42 5578.44,2648.14 5568.08,2648.14 5568.08,2658.5 5547.36,2658.5 5547.36,2648.14 5537,2648.14 5537,2627.42 ; 5537,2741.38 5557.72,2751.74 5578.44,2741.38 5568.08,2762.1 5578.44,2782.82 5557.72,2772.46 5537,2782.82 5547.36,2762.1 5537,2741.38 ; 5537,2876.06 5547.36,2876.06 5557.72,2865.7 5568.08,2876.06 5578.44,2876.06 5568.08,2886.42 5578.44,2896.78 5568.08,2896.78 5557.72,2907.14 5547.36,2896.78 5537,2896.78 5547.36,2886.42 5537,2876.06 ; 5537,3031.46 5578.44,3031.46 5557.72,2990.02 5537,3031.46 ; 5537,3114.34 5578.44,3114.34 5578.44,3155.78 5537,3155.78 5537,3114.34
  lines w12: 5480,2579.76 7508.45,2579.76 ; 5480,3325.68 7508.45,3325.68 ; 5827.99,2455.44 5827.99,3450 ; 6170.08,2455.44 6170.08,3450 ; 6816.72,2455.44 6816.72,3450 ; 7085.91,2455.44 7085.91,3450 ; 5480,2455.44 7508.45,2455.44 7508.45,3450 5480,3450 5480,2455.44
  text "Symbol" at 5554.59,3362.98 h72
  text "Quantity" at 5865.28,3362.98 h72
  text "Finished Hole Size" at 6207.38,3362.98 h72
  text "Plated" at 6854.02,3362.98 h72
  text "Hole Type" at 7123.21,3362.98 h72
  text "12" at 5865.28,3238.66 h60
  text "7.87mil (0.200mm)" at 6207.38,3238.66 h60
  text "PTH" at 6854.02,3238.66 h60
  text "Round" at 7123.21,3238.66 h60
  text "45" at 5865.28,3114.34 h60
  text "16.00mil (0.406mm)" at 6207.38,3114.34 h60
  text "PTH" at 6854.02,3114.34 h60
  text "Round" at 7123.21,3114.34 h60
  text "15" at 5865.28,2990.02 h60
  text "25.59mil (0.650mm)" at 6207.38,2990.02 h60
  text "PTH" at 6854.02,2990.02 h60
  text "Round" at 7123.21,2990.02 h60
  text "8" at 5865.28,2865.7 h60
  text "39.37mil (1.000mm)" at 6207.38,2865.7 h60
  text "PTH" at 6854.02,2865.7 h60
  text "Round" at 7123.21,2865.7 h60
  text "14" at 5865.28,2741.38 h60
  text "40.00mil (1.016mm)" at 6207.38,2741.38 h60
  text "PTH" at 6854.02,2741.38 h60
  text "Round" at 7123.21,2741.38 h60
  text "20" at 5865.28,2617.06 h60
  text "40.16mil (1.020mm)" at 6207.38,2617.06 h60
  text "PTH" at 6854.02,2617.06 h60
  text "Round" at 7123.21,2617.06 h60
  text "114 Total" at 5865.28,2492.74 h60
  text ".Layer_Name" at 577,-858.49 h60

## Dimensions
0,0 to 2300,0 on M2 Board Dimensions
0,0 to 0,2000 on M2 Board Dimensions
0,-400 to 1000,-400 on M2 Board Dimensions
